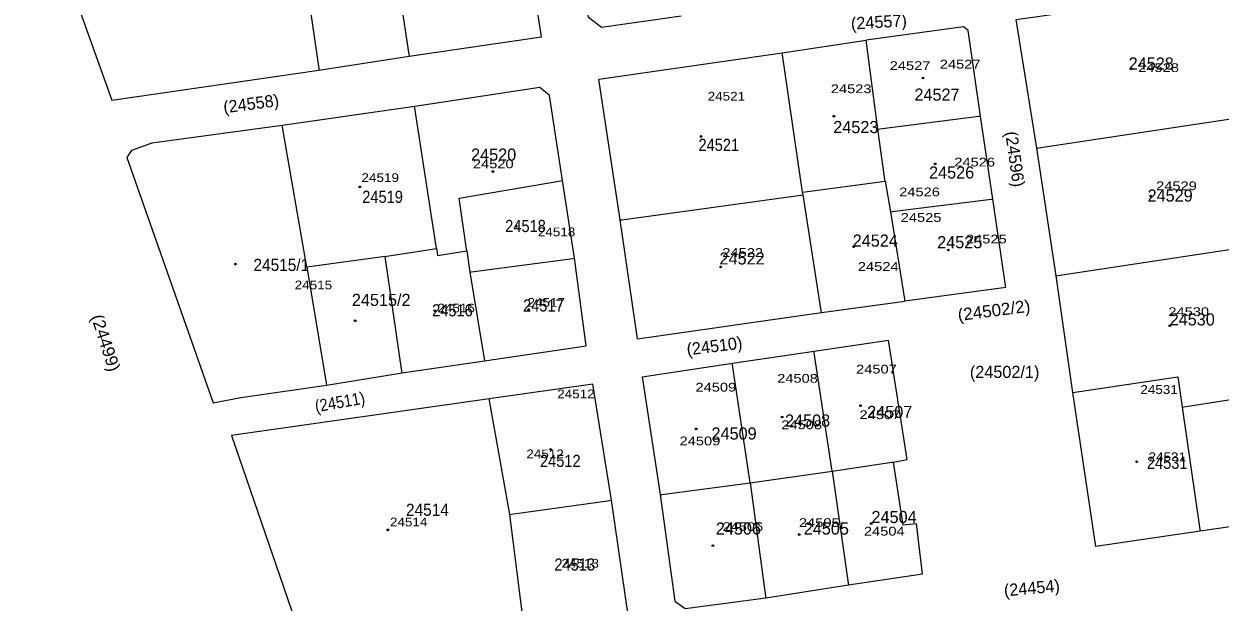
# Model space of a CAD drawing. Extents: x 649608 to 651081, y 237980 to 241202.
# Drawn here: x 649984.4 to 650339.2, y 239440.9 to 239612.2 of the extents above; entities that cross this region are included whole.
import ezdxf

# ---------------------------------------------------------------- set-up
doc = ezdxf.new("R2010")
doc.units = 0
doc.header["$PDMODE"] = 32
doc.header["$PDSIZE"] = 0.5
for name, color, linetype in [('19', 7, 'Continuous'), ('20', 7, 'Continuous'), ('6', 7, 'Continuous')]:
    doc.layers.add(name, color=color, linetype=linetype)
doc.layers.add('3', color=7, linetype='Continuous', lineweight=13)
doc.layers.add('5', color=7, linetype='Continuous', lineweight=13)

msp = doc.modelspace()

# ---------------------------------------------------------------- linework, layer by layer
at = {"layer": '3'}
for p, q in [((650263.101, 239611.317), (650234.213, 239607.38)), ((650166.408, 239518.905), (650161.253, 239554.117)), ((650275.649, 239534.083), (650245.704, 239530.088)), ((650167.84, 239507.598), (650173.133, 239472.727))]:
    msp.add_line(p, q, dxfattribs=at)
for points in [[(650179.344, 239614.539), (650155.782, 239611.169), (650151.895, 239614.146), (650148.688, 239634.921), (650144.994, 239659.482), (650141.507, 239684.319), (650137.863, 239708.628), (650133.916, 239733.418)], [(650037.18, 239671.542), (649984.431, 239663.354), (649995.856, 239630.494), (650010.549, 239589.669)], [(650098.716, 239602.658), (650137.995, 239608.441), (650131.305, 239651.053)], [(650284.846, 239575.429), (650278.795, 239613.56), (650341.039, 239622.462), (650346.869, 239584.804), (650352.295, 239546.902), (650358.829, 239503.479)], [(650268.174, 239584.935), (650264.499, 239610.312), (650263.101, 239611.317)], [(650161.253, 239554.117), (650154.941, 239595.894), (650209.347, 239603.616), (650234.213, 239607.38)], [(650010.549, 239589.669), (650071.957, 239598.504), (650098.716, 239602.658)], [(650144.198, 239565.783), (650140.356, 239591.026), (650137.435, 239593.341), (650100.353, 239587.744), (650061.025, 239582.162)], [(650061.025, 239582.162), (650022.387, 239576.904), (650016.373, 239574.751), (650014.981, 239572.617), (650040.569, 239499.945), (650048.801, 239501.553), (650074.151, 239505.212), (650096.642, 239508.791), (650121.073, 239512.356), (650151.229, 239516.789)], [(650275.649, 239534.083), (650271.806, 239560.329), (650268.174, 239584.935)], [(650295.601, 239502.951), (650290.624, 239537.573), (650284.846, 239575.429)], [(650151.229, 239516.789), (650147.724, 239542.812), (650144.198, 239565.783)], [(650166.408, 239518.905), (650221.019, 239526.727), (650245.704, 239530.088)], [(650167.84, 239507.598), (650194.572, 239511.702), (650218.799, 239515.243), (650240.93, 239518.547)], [(650242.375, 239482.383), (650246.39, 239483.109), (650240.93, 239518.547)], [(650153.145, 239505.429), (650122.411, 239501.121), (650046.003, 239490.267)], [(650132.999, 239431.986), (650163.748, 239436.339), (650158.694, 239471.073), (650153.145, 239505.429)], [(650333.35, 239461.895), (650302.406, 239457.327), (650295.601, 239502.951)], [(650358.829, 239503.479), (650364.595, 239466.403), (650333.35, 239461.895)], [(650046.003, 239490.267), (650068.149, 239425.852), (650072.472, 239423.448), (650132.999, 239431.986)], [(650229.032, 239445.95), (650250.99, 239449.261), (650249.16, 239464.101), (650245.199, 239463.677), (650242.375, 239482.383)], [(650173.133, 239472.727), (650177.495, 239441.151), (650180.595, 239439.009), (650204.517, 239442.103), (650229.032, 239445.95)]]:
    msp.add_lwpolyline(points, dxfattribs=at)
at = {"layer": '5'}
for p, q in [((650295.601, 239502.951), (650326.688, 239507.613)), ((650326.688, 239507.613), (650327.946, 239498.688))]:
    msp.add_line(p, q, dxfattribs=at)
for points in [[(650092.155, 239645.42), (650092.232, 239644.92), (650098.639, 239603.158), (650098.716, 239602.658)], [(650065.68, 239641.692), (650071.884, 239599.004), (650071.957, 239598.504)], [(650239.887, 239565.658), (650239.818, 239566.158), (650237.767, 239581.055), (650234.213, 239607.38)], [(650215.407, 239562.371), (650209.42, 239603.116), (650209.347, 239603.616)], [(650106.791, 239545.638), (650100.429, 239587.244), (650100.353, 239587.744)], [(650068.33, 239540.127), (650061.112, 239581.662), (650061.025, 239582.162)], [(650237.767, 239581.055), (650238.267, 239581.119), (650267.674, 239584.871), (650268.174, 239584.935)], [(650284.846, 239575.429), (650285.346, 239575.505), (650346.369, 239584.728), (650346.869, 239584.804)], [(650115.799, 239544.997), (650115.726, 239545.497), (650113.527, 239560.596), (650143.698, 239565.698), (650144.198, 239565.783)], [(650215.407, 239562.371), (650239.887, 239565.658), (650241.461, 239556.57), (650245.704, 239530.088)], [(650161.253, 239554.117), (650161.753, 239554.185), (650215.58, 239561.538)], [(650221.019, 239526.727), (650220.941, 239527.227), (650215.58, 239561.538), (650215.407, 239562.371)], [(650241.461, 239556.57), (650241.961, 239556.632), (650271.306, 239560.267), (650271.806, 239560.329)], [(650290.624, 239537.573), (650291.124, 239537.649), (650351.795, 239546.826), (650352.295, 239546.902)], [(650096.642, 239508.791), (650096.569, 239509.291), (650091.61, 239543.296), (650068.33, 239540.127)], [(650091.61, 239543.296), (650092.11, 239543.373), (650106.791, 239545.638)], [(650106.791, 239545.638), (650106.875, 239545.138), (650107.135, 239543.594), (650115.799, 239544.997), (650116.676, 239538.687), (650121.073, 239512.356)], [(650068.33, 239540.127), (650068.413, 239539.627), (650074.068, 239505.712), (650074.151, 239505.212)], [(650116.676, 239538.687), (650117.176, 239538.753), (650147.224, 239542.746), (650147.724, 239542.812)], [(650224.175, 239479.673), (650218.875, 239514.743), (650218.799, 239515.243)], [(650199.816, 239476.204), (650194.646, 239511.202), (650194.572, 239511.702)], [(650128.533, 239466.816), (650122.5, 239500.621), (650122.411, 239501.121)], [(650327.946, 239498.688), (650328.446, 239498.766), (650358.829, 239503.479)], [(650327.946, 239498.688), (650333.277, 239462.395), (650333.35, 239461.895)], [(650173.133, 239472.727), (650173.633, 239472.792), (650199.816, 239476.204), (650224.175, 239479.673)], [(650224.175, 239479.673), (650241.875, 239482.309), (650242.375, 239482.383)], [(650224.175, 239479.673), (650228.96, 239446.45), (650229.032, 239445.95)], [(650199.816, 239476.204), (650204.448, 239442.603), (650204.517, 239442.103)], [(650128.533, 239466.816), (650129.033, 239466.887), (650158.194, 239471.002), (650158.694, 239471.073)], [(650132.999, 239431.986), (650132.935, 239432.486), (650128.533, 239466.816)]]:
    msp.add_lwpolyline(points, dxfattribs=at)
at = {"layer": '6'}
for p in [(650251.134, 239596.186), (650312.897, 239598.945), (650224.676, 239584.875), (650185.248, 239578.866), (650123.545, 239568.467), (650254.727, 239570.752), (650084.093, 239563.935), (650318.635, 239561.188), (650130.511, 239552.235), (650230.551, 239546.192), (650258.651, 239545.208), (650047.132, 239541.053), (650191.099, 239540.221), (650106.274, 239527.214), (650134.153, 239527.584), (650082.682, 239524.254), (650324.335, 239522.795), (650232.581, 239499.11), (650209.341, 239495.723), (650183.813, 239492.214), (650140.675, 239486.122), (650314.492, 239482.47), (650092.369, 239462.284), (650235.767, 239464.166), (650214.404, 239460.888), (650188.801, 239457.606), (650146.015, 239451.529)]:
    msp.add_point(p, dxfattribs=at)

# ---------------------------------------------------------------- texts
at = {"layer": '19'}
for s, rotation, p in [('(24557)', 3.53, (650229.852, 239610.526)), ('24528', 359.954, (650312.126, 239598.702)), ('(24558)', 7.595, (650043.826, 239585.717)), ('(24596)', 278.041, (650275.479, 239580.128)), ('24529', 359.954, (650317.729, 239559.578)), ('24530', 359.954, (650324.283, 239522.865)), ('(24510)', 7.093, (650181.238, 239513.97)), ('(24454)', 5.109, (650275.29, 239442.542))]:
    msp.add_text(s, height=3.6, rotation=rotation, dxfattribs=at).set_placement(p)
for s, p in [('24527', (650248.576, 239589.48)), ('24523', (650224.49, 239579.866)), ('24520', (650117.07, 239571.695)), ('24526', (650252.911, 239566.407)), ('24524', (650230.27, 239546.218)), ('24525', (650255.319, 239545.738)), ('24522', (650190.771, 239540.931)), ('24515/2', (650081.712, 239528.631)), ('(24502/1)', (650265.023, 239507.3)), ('24507', (650234.556, 239495.441)), ('24508', (650210.188, 239492.882)), ('24509', (650188.385, 239489.042)), ('24504', (650235.839, 239464.297)), ('24506', (650189.668, 239460.884)), ('24505', (650215.746, 239460.884))]:
    msp.add_text(s, height=3.6, dxfattribs=at).set_placement(p)
for s, width, p in [('24521', 0.9, (650184.509, 239574.579)), ('24519', 0.9, (650084.796, 239559.197)), ('24518', 0.9, (650127.185, 239550.544)), ('24515/1', 0.95, (650052.521, 239539.008)), ('24516', 0.9, (650105.509, 239525.549)), ('24517', 0.9, (650132.485, 239526.991)), ('24512', 0.9, (650137.511, 239480.935)), ('24514', 0.95, (650097.752, 239466.431)), ('24513', 0.9, (650141.786, 239450.22))]:
    msp.add_text(s, height=3.6, dxfattribs=dict(at, width=width)).set_placement(p)
for s, rotation, width, p in [('(24502/2)', 7.408, 1.05, (650261.666, 239524.161)), ('(24499)', 288.056, 1.05, (650004.304, 239525.429)), ('(24511)', 10.134, 0.9, (650071.107, 239497.094)), ('24531', 359.954, 0.9, (650317.538, 239480.363))]:
    msp.add_text(s, height=3.6, rotation=rotation, dxfattribs=dict(at, width=width)).set_placement(p)
at = {"layer": '20'}
for s, width, p in [('24527', 1.25, (650241.232, 239598.571)), ('24527', 1.25, (650256.104, 239598.995)), ('24528', 1.25, (650314.943, 239597.967)), ('24523', 1.25, (650223.768, 239591.708)), ('24521', 1.15, (650187.246, 239589.491)), ('24520', 1.25, (650117.603, 239569.458)), ('24526', 1.25, (650260.396, 239569.978)), ('24519', 1.15, (650084.559, 239565.375)), ('24529', 1.25, (650320.26, 239562.947)), ('24526', 1.25, (650244.042, 239561.132)), ('24525', 1.25, (650244.505, 239553.563)), ('24518', 1.15, (650136.872, 239549.289)), ('24525', 1.25, (650263.869, 239547.169)), ('24522', 1.25, (650191.591, 239543.172)), ('24524', 1.25, (650231.799, 239539.032)), ('24515', 1.15, (650064.739, 239533.563)), ('24516', 1.15, (650107.06, 239526.719)), ('24517', 1.15, (650133.794, 239528.396)), ('24530', 1.25, (650323.886, 239525.645)), ('24507', 1.25, (650231.268, 239508.616)), ('24508', 1.25, (650207.851, 239505.891)), ('24509', 1.25, (650183.623, 239503.267)), ('24531', 1.15, (650315.584, 239502.569)), ('24512', 1.15, (650142.606, 239501.263)), ('24507', 1.25, (650232.289, 239495.105)), ('24508', 1.25, (650209.081, 239492.117)), ('24509', 1.25, (650178.895, 239487.336)), ('24512', 1.15, (650133.455, 239483.494)), ('24531', 1.15, (650318.023, 239482.634)), ('24514', 1.15, (650092.996, 239463.324)), ('24505', 1.25, (650214.299, 239463.132)), ('24506', 1.25, (650191.625, 239461.937)), ('24504', 1.25, (650233.589, 239460.592)), ('24513', 1.15, (650143.899, 239451.072))]:
    msp.add_text(s, height=2.6, dxfattribs=dict(at, width=width)).set_placement(p)

doc.saveas('drawing.dxf')
